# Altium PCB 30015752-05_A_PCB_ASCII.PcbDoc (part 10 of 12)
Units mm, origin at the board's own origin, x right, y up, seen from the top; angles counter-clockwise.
Board outline 100.05 x 72 mm, 10 copper layers (Top, GND_2, Signal_3, Signal_4, PWR_5, GND_6, Signal_7, Signal_8, GND_9, Bottom), stack 1.493 mm thick; 577 components, 546 nets, 2389 pads, 1412 vias.
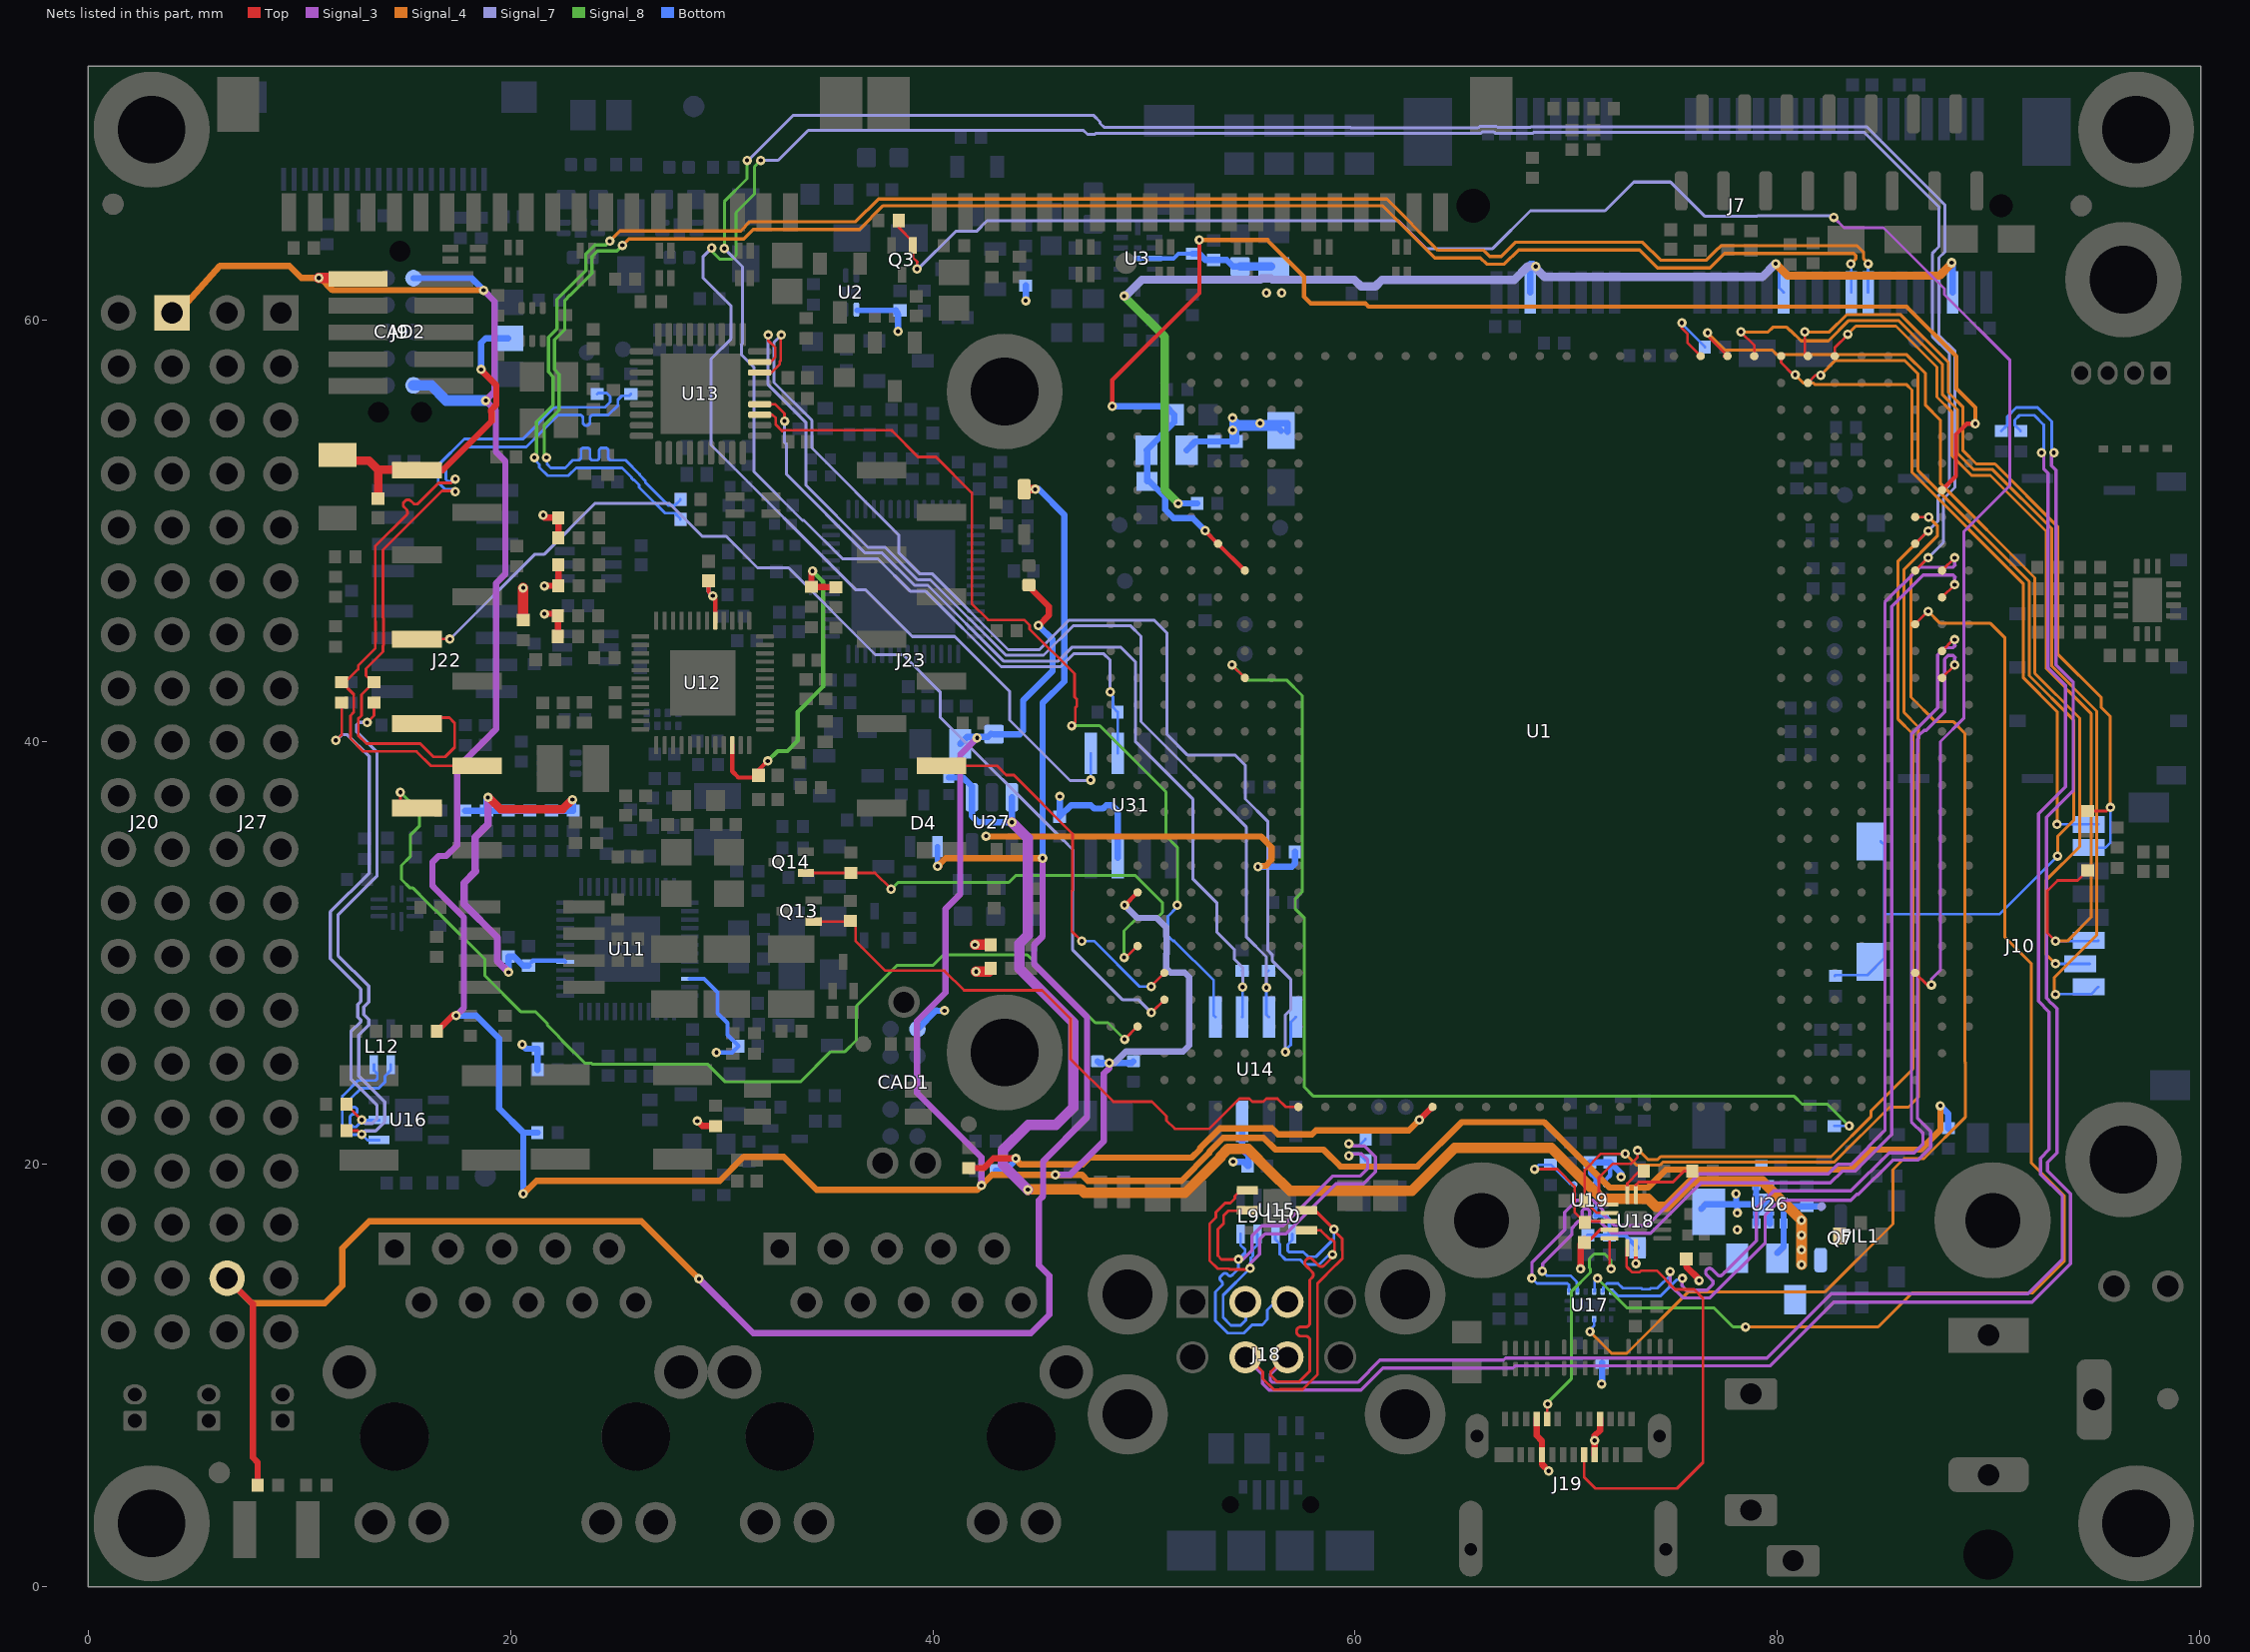
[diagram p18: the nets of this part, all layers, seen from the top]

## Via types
v1: diameter 0.45, hole 0.2, Top to Bottom, tented both sides, 1412 vias

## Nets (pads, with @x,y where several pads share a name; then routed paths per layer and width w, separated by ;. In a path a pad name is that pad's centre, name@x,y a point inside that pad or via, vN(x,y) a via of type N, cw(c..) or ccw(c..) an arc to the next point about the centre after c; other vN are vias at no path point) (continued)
USB_PCIe_D_N: J7.36 R229.2 | length 85.4
  Signal_8 w0.157: v1(21.7,53.475) 21.7,53.554 21.596,53.659 21.596,55.012 22.297,55.713 22.297,57.423 22.075,57.645 22.075,59.045 22.569,59.539 22.569,60.928 22.822,61.181 22.831,61.181 23.85,62.2 23.85,63 24.106,63.256 25.031,63.256 v1(25.3,63.525)
  Signal_4 w0.157: v1(25.3,63.525) 25.608,63.833 31.05,63.833 31.492,64.275 36.525,64.275 37.653,65.403 61.297,65.403 63.777,62.923 65.94,62.923 66.229,62.634 67.071,62.634 67.74,63.303 73.476,63.303 74.322,62.457 76.807,62.457 77.351,63.001 77.356,63.001 77.491,63.136 83.624,63.136 83.716,63.043 83.716,62.889 83.48,62.653 v1(83.48,62.64)
  Bottom w0.132: v1(21.7,53.475) 21.727,53.448 21.727,53.167 21.912,52.982 22.586,52.982 22.951,53.347 23.125,53.347 23.201,53.347 ccw(c23.201,53.476) 23.331,53.476 23.331,53.798 cw(c23.46,53.798) 23.46,53.928 23.633,53.928 cw(c23.633,53.798) 23.763,53.798 23.763,53.476 ccw(c23.892,53.476) 23.892,53.347 24.065,53.347 ccw(c24.065,53.476) 24.195,53.476 24.195,53.798 cw(c24.324,53.798) 24.324,53.928 24.497,53.928 cw(c24.497,53.798) 24.627,53.798 24.627,53.476 ccw(c24.757,53.476) 24.757,53.347 25.059,53.347 25.275,53.347 25.442,53.347 26.107,52.682 26.107,52.652 26.386,52.372 26.386,52.291 26.983,51.694 26.986,51.694 27.471,51.209 27.779,51.209 28.045,51.475 R229.2@28.045,51.5 ; v1(83.48,62.64) 83.49,62.64 83.5,62.65 83.5,62.64 J7.36@83.5,61.3
USB_PCIe_D_P: J7.38 R228.2 | length 85.2
  Signal_8 w0.157: v1(21.123,53.475) 21.123,53.554 21.227,53.659 21.227,55.164 22.013,55.949 22.013,57.306 21.791,57.528 21.791,59.163 22.201,59.573 22.201,60.976 23.566,62.341 23.566,63.118 23.988,63.54 24.515,63.54 v1(24.7,63.725)
  Signal_4 w0.157: v1(24.7,63.725) 25.176,64.201 30.897,64.201 31.34,64.643 36.347,64.643 37.423,65.719 61.502,65.719 63.93,63.291 66.092,63.291 66.382,63.002 66.918,63.002 67.588,63.671 73.629,63.671 74.475,62.825 76.654,62.825 77.198,63.369 77.203,63.369 77.338,63.504 83.776,63.504 84.084,63.196 84.084,62.889 84.3,62.673 v1(84.3,62.65)
  Bottom w0.132: v1(21.123,53.475) 21.123,53.389 21.358,53.154 21.358,53.015 21.76,52.614 22.739,52.614 23.103,52.978 25.29,52.978 25.739,52.529 25.739,52.499 25.817,52.421 25.849,52.421 26.094,52.176 26.094,52.062 26.83,51.326 26.834,51.326 27.319,50.841 27.779,50.841 28.045,50.575 R228.2@28.045,50.55 ; J7.38@84.3,61.3 v1(84.3,62.65)
USB_PWR: Q3.G R144.2 U1.C24 | length 93
  Top w0.127: R144.2@38.38,64.7 38.38,64.37 39.05,63.7 Q3.G@39.05,63.515 39.05,62.95 39.26,62.74 39.252,62.732 v1(39.252,62.403) ; U1.C24@86.53,29.07 87.1,28.5 v1(87.3,28.5)
  Signal_3 w0.142: v1(82.675,64.85) 83.165,64.36 85.029,64.36 87.912,61.476 87.912,61.188 91.019,58.081 91.019,52.156 88.843,49.98 88.843,41.143 87.725,40.025 87.725,29.2 87.3,28.775 v1(87.3,28.5)
  Signal_7 w0.142: v1(39.252,62.403) 39.257,62.403 39.28,62.38 41.088,64.188 42.067,64.188 42.566,64.687 62.056,64.687 63.369,63.374 66.518,63.374 68.31,65.165 71.842,65.165 73.2,66.523 74.937,66.523 76.551,64.909 79.056,64.909 79.067,64.92 82.605,64.92 v1(82.675,64.85)
USB_SS3_ALERT_N: R147.2 U1.C7 U18.10 | length 49.8
  Top w0.127: U18.10@72.05,17.7 71.455,17.7 R147.2@70.88,18.275 70.88,19.73 71.65,20.5 v1(72.8,20.5) ; U1.C7@86.53,50.66 87.165,50.66 v1(87.175,50.65)
  Signal_4 w0.142: v1(72.8,20.5) 73.342,19.958 74.439,19.958 74.584,20.102 82.702,20.102 85.313,22.713 86.213,22.713 86.69,23.19 86.69,40.71 85.994,41.406 85.994,48.173 87.573,49.752 87.573,50.252 v1(87.175,50.65)
USB_SS3_BUS_SEL: U1.C11 U17.12 | length 60.8
  Top w0.127: U1.C11@86.53,45.58 87.14,46.19 v1(87.15,46.19)
  Signal_8 w0.142: v1(71.48,14.6) 72.88,13.2 77,13.2 77.9,12.3 v1(78.5,12.3)
  Signal_4 w0.142: v1(78.5,12.3) 84.775,12.3 86.375,13.9 92.075,13.9 93.6,15.425 93.6,18.5 92.04,20.06 92.04,29.492 90.787,30.746 90.787,44.933 90.1,45.62 87.72,45.62 v1(87.15,46.19)
  Bottom w0.127: U17.12@71.325,13.975 71.353,14.003 71.353,14.473 v1(71.48,14.6)
USB_SS3_CC1: J19.A5 U18.13 | length 11.6
  Top w0.127: J19.A5@69.1,7.94 69.1,8.625 v1(69.125,8.65) ; U18.13@72.05,16.5 72.05,15.125 v1(72.125,15.05)
  Signal_8 w0.142: v1(69.125,8.65) 69.125,8.723 70.237,9.836 70.237,13.964 71.148,14.875 71.148,15.054 71.102,15.1 71.102,15.527 71.325,15.75 71.825,15.75 72.125,15.45 v1(72.125,15.05)
USB_SS3_CC2: J19.B5 U18.14 | length 20.4
  Top w0.127: J19.B5@70.85,6.24 70.85,5.175 71.375,4.65 75.25,4.65 76.479,5.879 76.479,13.655 76.055,14.079 75.175,14.079 74.289,14.965 73.553,14.965 73.472,14.884 73.128,14.884 72.884,15.128 72.884,15.15 72.859,15.175 72.859,16.009 U18.14@72.9,16.05
USB_SS3_INT_B: U1.C8 U18.9 U31.1 | length 164.5
  Top w0.127: U18.9@72.05,18.1 71.7,18.1 71.55,18.25 71.55,19.375 72.2,20.025 73.075,20.025 73.379,20.329 v1(73.379,20.651) ; U1.C8@86.53,49.39 87.14,50 v1(87.15,50)
  Signal_8 w0.142: v1(29.525,63.4) 29.525,63.25 29.9,62.875 30.5,62.875 30.675,63.05 30.675,65.075 31.55,65.95 31.55,67.25 v1(31.85,67.55)
  Signal_4 w0.142: v1(73.379,20.651) 73.449,20.651 73.873,20.227 74.328,20.227 74.472,20.371 82.545,20.371 84.447,22.274 84.447,22.547 86.421,24.521 86.421,40.379 85.725,41.075 85.725,48.575 v1(87.15,50)
  Signal_7 w0.142: v1(29.525,63.4) 29.127,63.002 29.127,61.973 30.45,60.65 30.45,59.1 29.5,58.15 29.5,54.065 36.364,47.202 36.823,47.202 39.025,45 41.04,45 43.641,42.399 43.641,41.039 46.503,38.177 47.452,38.177 v1(47.475,38.2) ; v1(31.85,67.55) 32.675,67.55 34.098,68.973 47.128,68.973 47.325,68.777 47.675,68.777 47.739,68.84 59.675,68.84 59.693,68.823 65.943,68.823 66.013,68.892 66.587,68.892 66.639,68.84 68.418,68.84 68.447,68.869 84.131,68.869 87.66,65.34 87.66,63.46 87.34,63.14 87.34,59.215 88.15,58.405 88.15,53.885 88.142,53.877 88.142,52.167 87.598,51.623 87.598,50.448 v1(87.15,50)
  Bottom w0.127: v1(47.475,38.2) 47.475,39.46 U31.1@47.485,39.47
USB_SS3_RX_N: U1.B12 U17.14 | length 46.7
  Top w0.132: U1.B12@87.8,44.31 88.373,44.883 v1@88.404,44.914 ; v1(88.404,44.852) v1@88.404,44.914 ; v1@88.41,44.92 v1@88.404,44.914
  Signal_3 w0.157: v1(75.5,14.6) 75.481,14.581 75.481,14.244 75.682,14.043 76.668,14.043 76.9,14.275 76.913,14.288 ccw(c76.799,14.401) 76.913,14.515 76.653,14.775 cw(c76.766,14.889) 76.653,15.003 76.678,15.028 cw(c76.792,14.914) 76.905,15.028 77.165,14.768 ccw(c77.279,14.882) 77.393,14.768 77.532,14.907 77.538,14.913 79.012,16.388 79.012,17.912 79.841,18.741 81.15,18.741 ; 81.151,18.74 83.484,18.74 85.294,20.55 86.482,20.55 86.9,20.968 86.9,21.475 86.354,22.021 86.354,39.642 86.36,39.649 86.36,40.005 86.354,40.012 86.354,40.375 87.6,41.621 87.6,44.122 87.947,44.469 88.328,44.469 88.42,44.561 88.404,44.577 v1(88.404,44.852)
  Bottom w0.132: U17.14@72.125,13.975 72.245,13.975 72.456,13.764 74.471,13.764 75.246,14.539 75.439,14.539 v1(75.5,14.6)
USB_SS3_RX_P: U1.B13 U17.13 | length 46.8
  Top w0.132: U1.B13@87.8,43.04 88.408,43.648 88.41,43.65 88.408,43.652 v1(88.404,43.652)
  Signal_3 w0.157: v1(74.925,14.925) 74.925,14.279 75.529,13.675 76.821,13.675 79.425,16.279 79.425,17.6 80.125,18.3 83.491,18.3 83.772,18.581 83.845,18.581 85.464,20.2 86.653,20.2 87.268,20.816 87.268,21.553 86.638,22.183 86.638,39.524 86.644,39.531 86.644,40.123 86.638,40.129 86.638,40.138 86.699,40.199 86.699,40.305 86.951,40.558 87.058,40.558 87.925,41.425 87.925,43.926 88.1,44.101 88.328,44.101 88.42,44.009 88.404,43.993 v1(88.404,43.652)
  Bottom w0.132: U17.13@71.725,13.975 71.757,14.007 71.757,14.178 71.934,14.354 72.454,14.354 72.677,14.132 73.556,14.132 73.605,14.083 73.952,14.083 74.001,14.132 74.318,14.132 74.925,14.739 v1(74.925,14.925)
USB_SS3_SCL: R173.2 U18.8 | length 1.3
  Top w0.127: U18.8@72.9,18.55 72.9,19.1 R173.2@73.45,19.65
USB_SS3_SDA: R174.2 U18.7 | length 3.4
  Top w0.127: U18.7@73.3,18.55 73.3,19.025 73.436,19.161 75.061,19.161 75.58,19.68 R174.2@75.98,19.68
USB_SS3_SW_PWR: R235.1 U1.C9 U17.3 U31.2 | length 172.9
  Top w0.127: U1.C9@86.53,48.12 87.14,48.73 v1(87.15,48.73)
  Signal_8 w0.142: v1(30.125,63.375) 30.125,65.597 31.2,66.672 v1(31.2,67.55)
  Signal_4 w0.142: v1(71.125,12.075) 72.15,11.05 72.875,11.05 75.775,13.95 82.25,13.95 85.475,17.175 85.475,19.75 86,20.275 86.95,20.275 88.902,22.227 88.902,24.826 88.875,24.854 88.875,40.425 88.325,40.975 87.475,40.975 86.325,42.125 86.325,47.905 v1(87.15,48.73)
  Signal_7 w0.142: v1(30.125,63.375) 30.988,62.512 30.988,58.877 30.948,58.837 30.948,58.327 31.525,57.75 31.525,52.802 33.825,50.502 33.898,50.502 35.725,48.675 37.4,48.675 38.925,47.15 39.652,47.15 43.232,43.569 46.056,43.569 46.662,44.175 48.1,44.175 48.4,43.875 v1(48.4,42.375) ; v1(31.2,67.55) 31.252,67.55 33.004,69.302 33.004,69.304 33.371,69.671 47.627,69.671 47.923,69.375 47.923,69.302 48.115,69.11 59.787,69.11 59.805,69.092 65.832,69.092 65.902,69.162 66.698,69.162 66.75,69.11 68.307,69.11 68.336,69.139 84.242,69.139 87.929,65.452 87.929,63.204 87.66,62.935 87.66,59.276 88.419,58.517 88.419,53.773 88.412,53.765 88.412,52.056 87.867,51.512 87.867,49.447 v1(87.15,48.73)
  Bottom w0.127: v1(48.4,42.375) 48.4,42.288 48.534,42.154 48.534,41.646 R235.1@48.755,41.425 U31.2@48.755,39.47 ; v1(71.125,12.075) 71.125,12.162 71.325,12.362 U17.3@71.325,12.675
USB_SS3_TX_N: U1.B9 U17.9 | length 54.1
  Top w0.132: U1.B9@87.8,48.12 88.406,48.726 v1@88.407,48.727 ; v1(88.404,48.727) v1@88.407,48.727 ; v1@88.41,48.73 v1@88.407,48.727
  Signal_3 w0.157: v1(68.375,14.6) 68.375,15.35 69.925,16.9 69.925,17.725 70.5,18.3 71.275,18.3 71.734,17.841 71.734,17.668 72.303,17.1 73.84,17.1 76.29,19.55 82.425,19.55 82.875,20 83.5,20 85.1,21.6 85.1,46.621 86.758,48.279 88.328,48.279 88.42,48.371 88.404,48.387 v1(88.404,48.727)
  Bottom w0.132: v1(68.375,14.6) 68.613,14.362 70.054,14.362 70.141,14.275 70.141,14.207 70.125,14.191 U17.9@70.125,13.975
USB_SS3_TX_P: U1.B10 U17.10 | length 53.2
  Top w0.132: U1.B10@87.8,46.85 88.403,47.453 v1@88.404,47.454 ; v1(88.404,47.452) v1@88.404,47.454 ; v1@88.41,47.46 v1@88.404,47.454
  Signal_3 w0.132: v1(68.875,14.95) v1@68.888,14.963
  Signal_3 w0.157: v1@68.888,14.963 68.888,15.3 70.272,16.684 70.272,16.979 70.575,17.3 70.593,17.3 ccw(c70.593,17.461) 70.754,17.461 70.754,17.735 cw(c70.915,17.735) 70.915,17.896 70.95,17.896 cw(c70.95,17.735) 71.111,17.735 71.111,17.461 ccw(c71.272,17.461) 71.272,17.3 71.469,17.3 71.475,17.3 71.582,17.3 72.15,16.732 73.993,16.732 76.386,19.125 82.521,19.125 83.077,19.681 83.681,19.681 85.425,21.425 85.425,46.425 86.911,47.911 88.328,47.911 88.42,47.819 88.404,47.803 v1(88.404,47.452)
  Bottom w0.132: v1(68.875,14.95) 69.095,14.73 70.206,14.73 70.509,14.428 70.509,14.207 70.525,14.191 U17.10@70.525,13.975
USBC_FAULT_N: R148.2 R149.2 U18.11 U19.A4 | length 7.7
  Top w0.127: v1(68.5,19.775) 69.575,19.775 70.396,18.954 70.396,17.734 R148.2@70.88,17.25 70.93,17.3 U18.11@72.05,17.3
  Bottom w0.127: v1(68.5,19.775) 68.705,19.98 R149.2@69.25,19.98 69.275,19.98 70.172,19.083 70.347,19.083 U19.A4@70.38,19.05
USBC_VBUS: C100.2 C103.2 C106.2 C107.2 D8.K J19.A4 J19.A9 J19.B4 J19.B9 U18.15 U19.C2 U19.D1 U19.D2 | length 12.9
  Top w0.2: v1(73.3,15.3) U18.15@73.3,16.05
  Top w0.3: J19.A4@68.6,7.94 68.6,7.15 68.85,6.9 J19.B9@68.85,6.24 68.85,5.8 v1(69.175,5.475) ; J19.B4@71.35,6.24 v1(71.35,6.925) 71.35,7.15 71.6,7.4 J19.A9@71.6,7.94 ; C100.2@75.69,15.525 75.69,15.16 76.3,14.55 v1@76.3,14.525
  Bottom w0.2: C107.2@71.025,16.635 C106.2@72.05,16.635 ; U19.C2@71.38,18.05 U19.D2@71.38,17.55 U19.D1@71.88,17.55 72.05,17.38 C106.2@72.05,16.635 ; v1(73.3,15.3) 73.3,15.92 73.275,15.945 D8.K@73.38,16.05 72.795,16.635 C106.2@72.05,16.635
  Bottom w0.3: v1(71.675,9.6) 71.7,9.625 C103.2@71.7,10.615
  other v1: 76.3,14.5
USBH1_D_N: J18.A2 L9.2 R242.1 U15.1 | length 24.9
  Top w0.132: U15.1@54.9,18.775 54.581,18.775 54.306,18.5 54.306,18.377 54.098,18.169 53.844,18.169 53.407,17.732 53.407,17.478 53.107,17.178 53.107,15.447 53.497,15.057 54.018,15.057 54.05,15.025 54.975,15.025 v1(55.025,15.075)
  Signal_3 w0.157: v1(55.025,15.075) 55.025,15.302 55.469,15.746 55.469,15.753 55.475,15.759 55.475,16.443 55.747,16.715 56.736,16.715 59.098,19.077 60.398,19.077 60.968,19.647 60.968,20.356 60.453,20.872 59.804,20.872 v1(59.7,20.976)
  Bottom w0.132: J18.A2@54.801,13.485 54.825,13.461 54.825,12.621 54.579,12.375 54.125,12.375 53.75,12.75 53.75,13.804 v1@55.023,15.077 ; v1@55.068,15.122 55.068,15.572 55.159,15.663 55.159,15.968 55.375,16.184 L9.2@55.375,16.7 ; v1(59.7,20.976) 59.804,20.872 60.167,20.872 R242.1@60.495,21.2
USBH1_D_P: J18.A3 L9.3 R243.1 U15.2 | length 24.8
  Top w0.132: v1(54.475,15.5) 53.675,15.5 53.5,15.675 53.5,16.925 53.775,17.2 53.775,17.579 53.997,17.801 54.876,17.801 U15.2@54.9,17.825
  Signal_3 w0.157: v1(54.475,15.5) 54.702,15.5 55.125,15.923 55.125,16.614 55.594,17.083 56.583,17.083 58.945,19.445 60.245,19.445 60.6,19.8 60.6,20.203 60.3,20.503 59.804,20.503 v1(59.7,20.399)
  Bottom w0.132: L9.3@54.575,16.7 54.575,16.184 54.791,15.968 54.791,15.816 v1(54.475,15.5) 54.475,15.05 54.262,14.837 54.175,14.75 cw(c54.083,14.842) 53.992,14.75 53.935,14.807 ccw(c53.843,14.715) 53.752,14.807 53.629,14.684 ccw(c53.721,14.593) 53.629,14.501 53.686,14.444 cw(c53.594,14.353) 53.686,14.261 53.625,14.2 53.382,13.957 53.382,12.597 53.972,12.007 54.732,12.007 55.124,12.399 55.599,12.399 55.85,12.65 55.85,13.1 56.235,13.485 J18.A3@56.801,13.485 ; v1(59.7,20.399) 59.804,20.503 60.167,20.503 R243.1@60.495,20.175
USBH1_OC_N: R142.1 U13.13 U14.2 | length 44.8
  Top w0.127: U13.13@31.8,56 32.525,56 32.975,55.55 v1(32.975,55.2)
  Signal_7 w0.142: v1(32.975,55.2) 32.975,54.198 33.073,54.1 33.073,52.677 36.794,48.956 37.601,48.956 39.137,47.419 39.763,47.419 43.344,43.838 45.944,43.838 46.606,44.5 48.894,44.5 49.591,43.803 49.591,40.031 52.311,37.311 52.311,33.524 53.46,32.375 53.46,30.99 54.271,30.179 54.271,29.729 54.675,29.325 v1(54.675,28.4)
  Bottom w0.127: R142.1@54.65,29.17 54.675,29.145 v1@54.675,28.405 ; U14.2@54.655,26.97 54.675,26.99 v1(54.675,28.4) v1@54.675,28.405 ; v1@54.655,28.425 v1@54.675,28.405
USBH1_PWR_EN: U13.12 U14.1 | length 43.7
  Top w0.127: U13.12@31.8,55.5 32.4,55.5 32.559,55.341 32.559,55.028 32.862,54.725 ; 32.85,54.775 38.063,54.775 ; 38.075,54.725 39.3,53.5 40.15,53.5 41.85,51.8 41.85,46.55 42.616,45.784 44.335,45.784 44.584,45.535 44.584,45.353 46.71,43.228 46.71,42.138 46.816,42.032 46.816,41.688 46.75,41.622 46.75,40.95 v1(46.575,40.775)
  Signal_8 w0.142: v1(46.575,40.775) 47.906,40.775 51.042,37.638 51.042,35.55 51.575,35.017 v1(51.575,32.275)
  Bottom w0.127: v1(51.575,32.275) 51.575,32.189 51.137,31.751 51.137,30.829 51.38,30.586 51.426,30.586 53.306,28.707 53.306,27.05 U14.1@53.385,26.97
USBH2_D_N: J18.B2 L10.2 R238.1 U15.5 | length 105.3
  Top w0.132: J18.B2@54.801,10.865 54.942,10.865 55.632,10.175 55.632,9.847 56.147,9.332 56.419,9.332 56.436,9.348 57.519,9.348 58.225,10.054 58.225,14.372 59.105,15.252 59.121,15.252 59.398,15.529 59.398,15.921 59.393,15.926 59.393,16.478 v1@58.973,16.898 ; U15.5@57.7,17.825 58.1,17.825 v1(59,16.925)
  Signal_3 w0.157: J18.B2@54.801,10.865 55.617,10.049 55.617,9.622 55.932,9.307 60.278,9.307 61.321,10.35 67.471,10.35 67.575,10.454 72.45,10.454 79.655,10.454 82.676,13.475 92.077,13.475 93.884,15.282 93.884,18.616 92.8,19.7 92.8,20.104 93.243,20.547 93.243,27.377 93.001,27.619 92.997,27.619 92.744,27.872 92.744,36.447 94.021,37.724 94.021,42.835 93.2,43.656 93.2,52.875 92.993,53.082 92.993,53.596 v1(93.098,53.7)
  Bottom w0.132: L10.2@57.025,16.7 57.025,16.425 56.809,16.209 56.809,15.9 56.859,15.85 57.553,15.85 57.778,15.625 58.15,15.625 59,16.475 v1(59,16.925) ; R238.1@90.605,54.73 90.881,55.006 90.881,55.403 91.322,55.843 92.328,55.843 92.993,55.178 92.993,53.804 v1(93.098,53.7)
USBH2_D_P: J18.B3 L10.3 R239.1 U15.4 | length 102.8
  Top w0.132: J18.B3@56.801,10.865 56.69,10.865 56,10.175 56,10 56.284,9.716 57.366,9.716 57.857,10.207 57.857,11.65 57.857,11.672 ccw(c57.662,11.672) 57.662,11.866 57.426,11.866 cw(c57.426,12.06) 57.232,12.06 57.232,12.104 cw(c57.426,12.104) 57.426,12.298 57.662,12.298 ccw(c57.662,12.493) 57.857,12.493 57.857,12.575 57.857,14.525 57.95,14.618 57.965,14.634 ccw(c57.828,14.771) 57.965,14.909 57.676,15.197 cw(c57.814,15.335) 57.676,15.472 57.707,15.503 cw(c57.844,15.365) 57.982,15.503 58.271,15.214 ccw(c58.408,15.352) 58.546,15.214 58.682,15.35 v1@58.991,15.659 ; U15.4@57.7,16.875 58.381,16.875 58.804,16.452 58.898,16.452 59.025,16.325 v1@59.025,15.725
  Signal_3 w0.157: J18.B3@56.801,10.865 55.985,10.049 55.985,9.775 56.085,9.675 60.125,9.675 61.175,10.725 67.029,10.725 67.126,10.822 79.502,10.822 82.555,13.875 91.875,13.875 93.5,15.5 93.5,18.5 92.468,19.532 92.468,20.293 92.875,20.7 92.875,27.224 92.376,27.723 92.376,36.6 93.653,37.877 93.653,42.683 92.825,43.51 92.825,52.729 92.625,52.929 92.625,53.596 v1(92.521,53.7)
  Bottom w0.132: L10.3@56.225,16.7 56.225,16.45 56.441,16.234 56.441,15.747 56.707,15.482 57.4,15.482 57.625,15.257 58.303,15.257 v1@58.848,15.802 ; v1@58.91,15.865 58.91,15.74 v1(58.925,15.725) ; R239.1@91.525,54.73 91.249,55.006 91.249,55.25 91.474,55.475 92.175,55.475 92.625,55.025 92.625,53.804 v1(92.521,53.7)
USBH2_OC_N: R143.1 U13.17 U14.3 | length 51.2
  Top w0.127: U13.17@31.8,58 32.3,58 32.541,58.241 32.541,58.685 32.2,59.025 v1(32.2,59.275)
  Signal_7 w0.142: v1(32.2,59.275) 32.2,56.923 34,55.123 34,52.15 36.925,49.225 37.739,49.225 39.276,47.688 39.875,47.688 43.455,44.108 45.25,44.108 46.642,45.5 49.375,45.5 49.86,45.015 49.86,40.965 54.84,35.985 54.84,30.785 55.8,29.825 v1(55.8,28.375)
  Bottom w0.127: R143.1@55.9,29.17 55.8,29.07 v1(55.8,28.375) 55.8,27.095 U14.3@55.925,26.97
USBH2_PWR_EN: U13.16 U14.4 | length 56.4
  Top w0.127: U13.16@31.8,57.5 32.35,57.5 32.75,57.9 32.75,58.027 32.795,58.072 32.795,59.245 v1(32.825,59.275)
  Signal_7 w0.142: v1(32.825,59.275) 32.475,58.925 32.475,57.029 34.269,55.235 34.269,53.925 38.4,49.794 38.4,48.945 39.387,47.958 39.986,47.958 43.567,44.377 45.052,44.377 46.45,45.775 50.475,45.775 51.1,45.15 51.1,40.35 52.075,39.375 54.325,39.375 54.8,38.9 54.8,37.3 55.875,36.225 55.875,30.131 56.069,29.937 56.069,29.651 56.948,28.772 56.948,27.321 56.7,27.073 v1(56.7,25.325)
  Bottom w0.127: v1(56.7,25.325) 56.7,25.396 56.959,25.654 56.959,26.733 U14.4@57.195,26.97
USDHC1_CD_B: J10.9 J10.10 R54.2 U1.G2 | length 49.8
  Top w0.127: U1.G2@81.45,57.01 81.815,57.375 v1(82.05,57.375)
  Signal_4 w0.142: v1(82.05,57.375) 82.751,58.076 86.022,58.076 86.65,57.448 86.65,52.881 91.931,47.6 91.931,43.142 94.006,41.067 ; v1(93.275,34.6) 93.275,35.527 94.051,36.303 94.051,41.022 94.006,41.067
  Bottom w0.127: R54.2@82.725,28.93 82.759,28.964 84.264,28.964 85.071,29.77 85.071,31.85 ; J10.10@84.9,35.3 85.071,35.129 85.071,31.85 ; v1(93.275,34.6) 90.52,31.845 85.698,31.845 85.692,31.85 85.071,31.85
USDHC1_CLK: R58.1 U1.L1 | length 3.5
  Top w0.127: v1(75.475,59.85) 75.475,59.603 75.747,59.33 75.747,58.903 U1.L1@76.37,58.28
  Bottom w0.127: v1(75.475,59.85) 75.475,59.82 76.57,58.725 R58.1@76.57,58.7
USDHC1_CMD: J10.3 R53.1 U1.F1 | length 45.1
  Top w0.127: U1.F1@82.72,58.28 82.72,58.67 83.34,59.29 v1(83.34,59.32) ; v1(93.175,30.575) 92.784,30.966 92.784,32.959 93.275,33.45 94.23,33.45 R53.1@94.7,33.92
  Signal_4 w0.142: v1(83.34,59.32) 83.718,59.698 85.625,59.698 87.562,57.762 87.562,56.336 88.258,55.639 88.258,53.574 89.202,52.631 90.088,52.631 92.738,49.981 92.738,43.477 94.813,41.402 94.859,41.356 94.859,31.694 93.74,30.575 v1(93.175,30.575)
  Bottom w0.127: v1(93.175,30.575) 95.175,30.575 J10.3@95.2,30.6
USDHC1_DATA0: J10.7 R55.1 U1.G1 | length 37.5
  Top w0.127: v1(81.3,59.425) 81.3,58.43 U1.G1@81.45,58.28 ; R55.1@94.7,36.73 95.605,36.73 v1(95.775,36.9)
  Signal_4 w0.142: v1(81.3,59.425) 82.466,59.425 83.277,60.237 85.848,60.237 88.1,57.985 88.1,56.559 88.797,55.862 88.797,53.798 89.425,53.17 90.311,53.17 93.277,50.204 93.277,44.178 95.352,42.103 95.352,41.625 95.775,41.202 v1(95.775,36.9)
  Bottom w0.127: J10.7@95.2,35 95.55,35 95.775,35.225 v1(95.775,36.9)
USDHC1_DATA1: J10.8 U1.H1 | length 32.4
  Top w0.127: U1.H1@80.18,58.28 80.18,57.97 80.756,57.394 v1(80.844,57.394)
  Signal_4 w0.142: v1(80.844,57.394) 81.242,56.995 81.716,56.995 81.771,56.94 86.11,56.94 86.375,56.675 86.375,52.775 91.661,47.489 91.661,43.031 93.25,41.442 v1(93.25,36.1)
  Bottom w0.127: v1(93.25,36.1) J10.8@94.75,36.1 J10.8@95.2,36.1
USDHC1_DATA2: J10.1 U1.J1 | length 49
  Top w0.127: v1(78.275,59.425) 78.91,58.79 U1.J1@78.91,58.28
  Signal_4 w0.142: v1(78.275,59.425) 79.57,59.425 79.788,59.643 80.452,59.643 80.615,59.48 80.647,59.48 81.125,59.002 82.423,59.002 83.389,59.967 85.737,59.967 87.831,57.873 87.831,56.447 88.528,55.75 88.528,53.686 89.313,52.9 90.199,52.9 93.008,50.092 93.008,43.588 95.083,41.513 95.128,41.468 95.128,30.855 93.129,28.855 93.129,28.096 v1(93.175,28.05)
  Bottom w0.127: v1(93.175,28.05) 93.189,28.063 94.864,28.063 J10.1@95.2,28.4
USDHC1_DATA3: J10.2 U1.K1 | length 46.2
  Top w0.127: v1(76.7,59.375) 76.7,59.22 U1.K1@77.64,58.28 U1.K1@77.48,58.28
  Signal_4 w0.142: v1(76.7,59.375) 77.516,58.559 79.766,58.559 79.98,58.345 86.134,58.345 87.023,57.456 87.023,55.949 87.72,55.252 87.72,52.259 92.2,47.779 92.2,43.254 94.275,41.179 94.32,41.133 94.32,35.047 92.752,33.478 92.752,29.923 v1(93.175,29.5)
  Bottom w0.127: v1(93.175,29.5) J10.2@94.35,29.5 J10.2@94.8,29.5
USER_LED0: Q14.G R108.1 U1.AM23 | length 22.8
  Top w0.127: Q14.G@33.99,33.8 R108.1@36.12,33.8 37.26,33.8 v1(38.025,33.035) ; v1(49.06,29.8) 49.16,29.8 U1.AM23@49.7,30.34
  Signal_8 w0.142: v1(38.025,33.035) 38.035,33.035 38.35,33.35 43.6,33.35 43.925,33.675 49.6,33.675 50.875,32.4 50.875,31.925 50.65,31.7 49.7,31.7 49.06,31.06 v1(49.06,29.8)
USER_LED1: Q13.G R109.1 U1.AF29 | length 29.6
  Top w0.127: Q13.G@34.35,31.5 36.08,31.5 R109.1@36.1,31.52 36.125,31.52 36.346,31.299 36.346,30.569 37.741,29.175 40.55,29.175 41.48,28.245 45.18,28.245 46.525,26.9 46.525,24.987 48.548,22.964 50.373,22.964 51.066,22.272 51.066,22.077 51.458,21.684 53.092,21.684 54.518,23.11 54.987,23.11 55.133,22.964 55.651,22.964 55.797,23.11 56.326,23.11 56.717,22.72 U1.AF29@57.32,22.72
VCC_LICELL: D4.1 D13.K J27.38 R18.1 | length 104.5
  Top w0.3: J27.38@6.56,14.6 7.787,13.373 7.787,6.121 8.02,5.888 R18.1@8.02,4.8
  Top w0.4: D13.K@44.325,51.97 v1(44.85,51.97)
  Signal_3 w0.3: v1(28.925,14.575) 31.5,12 44.65,12 45.525,12.875 45.525,14.725 45.025,15.225 45.025,18.3 45.223,18.498 45.223,20.148 47.308,22.233 47.308,26.982 44.798,29.492 44.798,30.398 45.2,30.8 v1(45.2,34.5)
  Signal_4 w0.3: J27.38@6.56,14.6 7.737,13.423 11.198,13.423 12.033,14.258 12.033,16.033 13.3,17.3 26.2,17.3 28.962,14.537 28.925,14.5 v1(28.925,14.575) ; v1@40.319,34.119 v1(40.219,34.119) 40.6,34.5 v1(45.2,34.5)
  Bottom w0.25: v1(40.219,34.119) D4.1@40.219,35.059
  Bottom w0.3: v1(44.85,51.97) 45.015,51.97 46.225,50.76 46.225,42.875 45.2,41.85 v1(45.2,34.5)
VCC_MCA: C143.2 C162.2 CAD2.1 CAD2.5 J9.1 J20.1 R15.2 R17.2 R31.2 R162.2 R259.2 R260.2 U1.AM21 | length 208.2
  Top w0.2: v1(49.08,32.27) 49.09,32.27 U1.AM21@49.7,32.88
  Top w0.3: R15.2@16.5,26.3 17.25,27.05 v1(17.425,27.05) ; C162.2@44.55,47.44 44.55,47.373 45.502,46.421 45.502,46.005 45.022,45.525 v1(45,45.525)
  Top w0.5: v1(10.92,61.98) 12.728,61.98 J9.1@12.768,61.94
  Signal_3 w0.3: v1(17.425,27.05) 17.791,27.416 17.791,31.692 16.475,33.009 16.475,33.015 16.299,33.191 16.299,34.31 16.593,34.604 16.954,34.604 17.468,35.118 17.468,38.768 19.313,40.613 19.313,47.516 19.75,47.953 19.75,53.3 19.3,53.75 19.3,55.7 v1(18.825,56.175) 19.25,56.6 19.25,60.875 v1(18.725,61.4) ; v1(42.1,40.2) 41.3,39.4 41.3,32.8 40.6,32.1 40.6,28.143 39.25,26.793 39.25,23.375 42.3,20.325 v1(42.3,19) ; v1(45.8,19.5) 46.5,19.5 48.1,21.1 48.1,24.3 48.352,24.552 v1(48.352,24.801)
  Signal_4 w0.3: J20.1@4.325,60.425 6.226,62.546 9.519,62.546 10.086,61.98 v1(10.92,61.98) 10.985,61.98 11.565,61.4 v1(18.725,61.4) ; v1(20.6,18.6) 21.227,19.227 29.91,19.227 31.031,20.348 32.943,20.348 34.491,18.8 42.1,18.8 v1(42.3,19) 42.8,19.5 v1(45.8,19.5) 47.07,19.5 47.345,19.225 51.78,19.225 53.096,20.541 53.096,20.593 53.757,21.254 55.671,21.254 56.225,20.7 58.5,20.7 59.303,19.897 62.947,19.897 65.05,22 68.95,22 72.052,18.898 73.872,18.898 74.728,19.754 83.454,19.754 84.4,20.7 86.8,20.7 87.725,21.625 v1(87.725,22.775)
  Signal_7 w0.3: v1(48.352,24.801) 48.601,24.801 49.15,25.35 51.85,25.35 52.136,25.636 52.136,28.864 51.925,29.075 51.271,29.075 51.051,29.296 51.051,29.959 51.071,29.98 51.071,30.773 51.051,30.794 51.051,31.224 50.6,31.675 49.675,31.675 v1(49.08,32.27)
  Bottom w0.3: CAD2.1@15.4,61.97 18.155,61.97 v1(18.725,61.4) ; v1(17.425,27.05) 18.36,27.05 19.45,25.96 19.45,22.65 20.6,21.5 ; v1(20.6,18.6) 20.6,21.5 ; R17.2@21.27,21.5 20.6,21.5 ; R31.2@41.3,39.92 41.63,40.25 42.61,40.25 C143.2@42.75,40.39 ; C143.2@42.9,40.37 44.12,40.37 44.275,40.525 44.275,41.975 45.675,43.375 45.675,44.85 v1(45,45.525) ; R260.2@47.8,24.88 47.88,24.8 47.881,24.801 v1(48.352,24.801) 49.419,24.801 49.42,24.8 R259.2@49.5,24.88 ; v1(87.725,22.775) 88.1,22.4 R162.2@88.1,21.705
  Bottom w0.5: CAD2.5@15.4,56.89 16.235,56.89 16.95,56.175 v1(18.825,56.175)
VCC_SCU_1V8: CAD1.1 R14.1 R32.2 R35.2 R36.1 R38.1 R51.2 U1.AA29 | length 46.5
  Top w0.3: v1(28.85,22.05) 29.08,21.82 R35.2@29.7,21.82 ; R32.2@41.7,19.82 42.42,19.82 42.876,20.276 v1(43.927,20.276) ; v1(63.05,22.11) 63.66,22.72 U1.AA29@63.67,22.72
  Top w0.5: v1(42,30.4) R38.1@42.74,30.4 ; v1(42.052,29.126) 42.666,29.126 R36.1@42.74,29.2
  Signal_4 w0.3: v1(42.525,35.55) 42.55,35.525 55.55,35.525 56.05,35.025 56.05,34.425 55.754,34.129 55.429,34.129 v1(55.4,34.1) ; v1(43.927,20.276) 43.927,20.233 44.158,20.002 45.592,20.002 ; 45.592,20.002 47.102,20.002 47.423,20.323 52.274,20.323 52.669,20.718 52.669,20.77 53.599,21.7 56.075,21.7 56.35,21.425 57.96,21.425 58.143,21.608 62.548,21.608 v1(63.05,22.11)
  Bottom w0.3: CAD1.1@39.27,26.41 39.285,26.41 40.175,27.3 40.2,27.275 v1(40.55,27.275) ; R14.1@42.98,19.7 43.41,19.7 43.927,20.217 v1(43.927,20.276) ; v1(55.4,34.1) 57.006,34.1 57.155,34.249 R51.2@57.155,34.8
VDDH1: C53.2 R90.2 R100.2 U11.10 | length 7.5
  Bottom w0.2: U11.10@28.49,28.792 29.168,28.792 29.808,28.152 29.808,27.162 30.275,26.695 30.275,26.125 30.79,25.61 C53.2@30.79,25.6 30.49,25.3 v1(29.75,25.3)
  Bottom w0.3: v1(20.551,25.676) 20.551,25.649 20.725,25.475 R100.2@21.28,25.475 R90.2@21.28,24.475
VDDH2: C71.2 R122.2 R132.2 U12.10 | length 16
  Top w0.2: U12.10@30.5,39.85 30.5,38.611 30.788,38.323 31.663,38.323 31.74,38.4 31.74,38.665 v1(32.175,39.1)
  Top w0.3: R132.2@34.245,47.355 34.265,47.335 R122.2@35.225,47.335 ; R132.2@34.25,47.36 34.25,48.05 v1(34.3,48.1) ; R122.2@35.2,47.36 R122.2@35.225,47.335 ; R122.2@35.4,47.335 R122.2@35.225,47.335
  Signal_8 w0.2: v1(32.175,39.1) 32.65,39.575 32.736,39.575 32.738,39.573 33.112,39.573 33.6,40.061 33.6,41.425 34.8,42.625 34.8,47.6 v1(34.3,48.1)
VDDIO1: C51.2 C52.2 R86.2 R88.2 R92.2 R94.2 R96.2 R98.2 U11.29 | length 22.9
  Top w0.4: v1(18.926,37.377) 18.963,37.377 19.515,36.825 22.48,36.825 v1(22.93,37.275)
  Signal_3 w0.35: v1(18.926,37.377) 18.926,36.129 18.94,36.115 18.324,35.499 18.324,33.933 18.35,33.907 18.35,33.875 17.801,33.326 17.801,32.322 19.373,30.75 19.373,29.627 v1(19.9,29.1)
  Bottom w0.2: R88.2@19.89,36.752 R88.2@19.9,36.762 ; C52.2@20.998,29.592 21.058,29.652 22.53,29.652 U11.29@22.59,29.592
  Bottom w0.3: R98.2@17.84,36.752 R94.2@18.865,36.752 ; v1(18.926,37.377) 18.917,37.377 18.865,37.325 R94.2@18.865,36.752 ; v1(19.9,29.1) C51.2@19.9,29.84 20.16,29.84 20.585,29.415 C52.2@20.85,29.415 ; R86.2@20.915,36.752 R88.2@19.89,36.752 R94.2@18.865,36.752 ; R92.2@21.94,36.752 R96.2@22.965,36.752 22.965,37.24 v1(22.93,37.275)
VDDIO2: C69.2 C70.2 R118.2 R120.2 R124.2 R126.2 R128.2 R130.2 U12.29 | length 7.9
  Top w0.2: C70.2@29.375,47.64 29.375,47.125 v1(29.575,46.925) 29.7,46.8 U12.29@29.7,45.75
  Top w0.3: v1(21.547,50.751) 21.547,50.678 21.6,50.625 R130.2@22.265,50.625 ; v1(21.6,46.075) 22.24,46.075 R128.2@22.24,45.1 ; v1(21.6,47.4) R118.2@22.265,47.4 R120.2@22.265,48.4 ; R126.2@22.265,49.625 R126.2@22.265,49.675 R130.2@22.265,50.625
  Bottom w0.2: C69.2@29.375,47.64 29.375,47.125 v1(29.575,46.925)
VIN: C4.2 FIL1.3 Q7.2 R19.2 R21.2 R22.1 U26.4 U26.8 U27.1 U27.3 | length 75.5
  Signal_3 w0.5: v1(43.75,36.2) 44.507,35.443 44.507,30.852 44.1,30.445 44.1,29.275 46.65,26.725 46.65,22.7 45.825,21.875 44.525,21.875 43.325,20.675 43.325,19.975 v1(44.5,18.8)
  Signal_4 w0.5: v1(44.5,18.8) 44.527,18.827 46.998,18.827 47.172,18.653 51.953,18.653 53.623,20.323 53.623,20.374 53.976,20.727 54.923,20.727 55.973,19.677 55.973,19.676 56.911,18.738 62.688,18.738 64.725,20.775 69.295,20.775 71.699,18.371 73.878,18.371 74.251,17.998 74.749,17.998 75.953,19.202 79.298,19.202 v1(81.15,17.35) v1(81.15,16.65) 81.15,15.85 v1(81.15,15.25)
  Signal_7 w0.4: 82.073,17.993 82.1,18.02
  Bottom w0.3: C4.2@40.75,38.32 41.43,38.32 41.85,37.9 U27.1@41.85,37.38 41.85,36.5 42.15,36.2 v1(43.75,36.2) U27.3@43.75,37.38 ; R22.1@80,15.8 80.3,16.1 U26.4@80.3,17.19 U26.8@80.3,18.1 80.38,18.02 R21.2@81.4,18.02 82.1,18.02
  other v1: 81.15,15.95
VIN_PROT: C1.1 C2.2 C3.2 C6.2 C10.2 C11.2 C12.2 C84.1 C99.2 C104.2 C105.2 C142.2 C147.2 D14.K R1.1 R22.2 R43.2 R47.2 R190.1 U2.3 U3.3 U3.14 U14.7 U18.12 U19.A1 U19.A2 U26.1 U26.2 U26.5 U26.6 U26.7 U31.7 | length 46.5
  Top w0.15: C99.2@70.86,16.45 71.15,16.45 71.6,16.9 U18.12@72.05,16.9
  Top w0.3: v1(70.678,15.051) 70.678,16.218 70.875,16.415 70.85,16.44 C99.2@70.86,16.45
  Top w0.5: R190.1@20.6,45.78 v1(20.6,47.3)
  Bottom w0.2: U3.14@49.7,62.9 U3.3@50.5,62.9 51.4,62.9 51.63,63.13 R43.2@52.3,63.13 ; C104.2@71.13,20.09 71.13,19.57 71.38,19.32 U19.A2@71.38,19.05 ; U19.A1@71.88,19.05 71.88,19.28 72.08,19.48 C105.2@72.08,20.09
  Bottom w0.25: U2.3@36.4,60.44 C6.2@38.25,60.44
  Bottom w0.3: C6.2@38.25,60.44 38.303,60.352 38.325,60.315 38.3,60.29 38.352,60.238 v1(38.352,59.453) ; v1(44.4,60.9) R47.2@44.4,61.62 ; C147.2@46,36.46 C147.2@46.02,36.48 ; v1(46.02,37.42) C147.2@46.02,36.48 ; U31.7@48.755,34.53 48.755,36.745 48.49,37.01 48.22,37.01 48.06,36.85 47.644,36.85 47.484,37.01 46.55,37.01 C147.2@46.02,36.48 ; R1.1@52.025,53.825 52.435,54.235 C2.2@53.325,54.235 C3.2@54.375,54.235 ; R43.2@52.3,63.13 52.62,63.13 52.91,62.84 C12.2@53.3,62.84 53.91,62.84 54.22,62.53 C11.2@54.55,62.53 ; v1(54.225,20.125) 54.715,20.125 C84.1@54.915,19.925 ; U14.7@54.655,21.63 54.655,20.695 54.95,20.4 C84.1@54.95,19.925 ; C1.1@56.5,54.75 56.375,54.875 v1@54.375,54.875 ; C1.1@56.8,54.7 56.8,55.1 v1(55.5,55.1) 54.45,55.1 ; C104.2@71.13,20.09 C105.2@72.08,20.09 72.6,19.57 v1(72.6,19.4) ; D14.K@76.4,17.9 76.6,18.1 78.05,18.1 ; v1(78.05,18.6) 78.05,18.1 ; v1(78.1,17.7) 78.1,18.05 78.05,18.1 ; U26.6@79,17.19 79,17.75 U26.7@79.35,18.1 ; U26.1@79,19.01 79,18.45 U26.7@79.35,18.1 ; U26.5@79.65,17.19 79.65,17.8 U26.7@79.35,18.1 ; U26.2@79.65,19.01 79.65,18.4 U26.7@79.35,18.1 ; v1(54.2,54.775) v1@54.2,54.85 ; v1(54.2,54.775) 54.2,54.41 C3.2@54.375,54.235 ; v1(54.2,54.775) 54.3,54.875 v1@54.375,54.875 ; v1@54.2,54.85 54.2,55.1 ; v1@54.2,54.85 54.375,55.025 ; 54.2,55.1 54.45,55.1 ; 54.2,55.1 v1(54.2,55.35) 54.45,55.1 ; C3.2@54.375,54.235 v1@54.375,54.875 ; v1@54.375,54.875 54.375,55.025 ; 54.375,55.025 54.45,55.1 ; 78.05,18.1 U26.7@79.35,18.1
  Bottom w0.4: C11.2@54.55,62.53 C10.2@56.02,62.53
  other v1: 78.1,16.9 55.8,61.275 56.525,61.275
VLDO2_VSELECT: R232.1 U1.AH13 | length 50.9
  Top w0.127: v1(54.17,43.66) 54.17,43.65 U1.AH13@54.78,43.04
  Signal_8 w0.142: v1(54.17,43.66) 54.891,42.939 56.76,42.939 57.5,42.198 57.5,32.91 57.175,32.585 57.175,32.09 57.6,31.665 57.6,23.65 58.032,23.218 80.802,23.218 81.169,22.851 82.374,22.851 v1(83.4,21.825)
  Bottom w0.127: R232.1@82.7,21.82 82.705,21.825 v1(83.4,21.825)
VLDO4_1V5: J7.6 J7.28 J7.48 R205.1 | length 57.5
  Signal_8 w0.4: v1(49.06,61.12) 50.98,59.2 50.98,51.945 v1(51.625,51.3)
  Signal_4 w0.4: v1(79.925,62.65) 80.487,62.088 87.688,62.088 88.254,62.654 v1(88.254,62.703)
  Signal_7 w0.4: v1(49.06,61.12) 49.12,61.12 49.9,61.9 55.519,61.9 55.571,61.952 56.029,61.952 56.081,61.9 59.964,61.9 60.285,61.579 60.965,61.579 61.279,61.893 67.543,61.893 68.177,62.527 v1(68.554,62.527) 68.554,62.446 68.98,62.02 79.281,62.02 79.911,62.65 v1(79.925,62.65)
  Bottom w0.127: v1(79.925,62.65) 79.925,62.563 80.089,62.399 80.089,61.511 J7.28@80.3,61.3
  Bottom w0.3: v1(51.625,51.3) R205.1@52.52,51.3 ; J7.6@68.3,61.3 68.3,62.65 68.431,62.65 v1(68.554,62.527) ; v1(88.254,62.703) 88.297,62.703 88.3,62.7 J7.48@88.3,61.3
VSYS: R1.2 R219.1 R220.1 U1.AH9 U1.AJ8 U1.B6 | length 69.5
  Top w0.2: v1(48.5,55.9) 48.5,57.139 52.625,61.264 v1(52.625,63.775) ; v1(52.9,50.01) 52.9,50 U1.AJ8@53.51,49.39 U1.AH9@54.78,48.12 ; U1.B6@87.8,51.93 88.46,52.59 88.46,54.56 88.974,55.074 v1(89.381,55.074)
  Signal_4 w0.2: v1(52.625,63.775) 55.85,63.775 57.58,62.045 57.58,61.1 57.905,60.775 60.488,60.775 60.638,60.625 86.125,60.625 88.48,58.27 88.48,56.74 89.381,55.839 v1(89.381,55.074)
  Bottom w0.3: v1(48.5,55.9) 51.04,55.9 R220.1@51.44,55.5 51.44,55.14 R1.2@50.125,53.825 50.15,53.8 R219.1@50.15,52.444 ; R219.1@50.15,52.35 R219.1@50.15,52.444 ; v1(52.9,50.01) 52.31,50.6 51.4,50.6 51,51 51,51.594 R219.1@50.15,52.444
XBEE/EXPANSION_USB2_D_N: L12.2 R77.1 R79.1 U16.5 | length 31.4
  Top w0.132: v1(11.725,40.075) 12,40.35 R77.1@12,41.87 ; R79.1@12.23,22.85 12.23,22.82 v1(12.95,22.1)
  Signal_7 w0.157: v1(11.725,40.075) 12,40.35 12.275,40.35 13.3,39.325 13.3,33.8 11.457,31.957 11.457,29.743 12.907,28.293 12.907,27.719 12.76,27.573 12.76,26.98 12.907,26.834 12.907,26.753 12.441,26.287 12.441,24.034 13.675,22.8 13.675,22.172 13.45,21.947 13.103,21.947 v1(12.95,22.1)
  Bottom w0.132: U16.5@13.775,22.1 v1(12.95,22.1) 12.95,22.05 12.675,21.775 12.55,21.775 12.4,21.925 12.4,22.225 12.4,22.227 cw(c12.549,22.227) 12.549,22.377 12.59,22.377 ccw(c12.59,22.526) 12.739,22.526 12.739,22.56 ccw(c12.59,22.56) 12.59,22.709 12.549,22.709 cw(c12.549,22.858) 12.4,22.858 12.4,22.875 12.4,23.079 12.928,23.607 13.757,23.607 14.05,23.9 14.05,24.175 14.325,24.45 L12.2@14.325,24.727
XBEE/EXPANSION_USB2_D_P: L12.3 R76.1 R78.1 U16.4 | length 31.5
  Top w0.132: R78.1@12.23,21.6 12.775,21.6 v1(12.95,21.425) ; v1(13.2,40.925) 13.525,41.25 R76.1@13.525,41.87
  Signal_7 w0.157: v1(12.95,21.425) 13.103,21.578 13.603,21.578 14.043,22.019 14.043,22.953 12.809,24.187 12.809,26.134 13.275,26.6 13.275,26.868 13.045,27.098 13.045,27.455 13.275,27.685 13.275,28.446 11.825,29.896 11.825,31.804 13.668,33.647 13.668,39.532 12.7,40.5 12.7,40.8 12.825,40.925 v1(13.2,40.925)
  Bottom w0.132: L12.3@13.525,24.727 13.525,24.45 13.682,24.293 13.682,24.053 13.604,23.975 12.775,23.975 12.032,23.232 12.032,21.772 12.397,21.407 12.828,21.407 12.898,21.477 v1(12.95,21.425) 13.225,21.15 U16.4@13.775,21.15
XBEE_D_N: J22.8 R77.2 R240.2 | length 34.7
  Top w0.132: v1(17.38,52.46) 17.188,52.268 16.591,52.268 15.712,51.388 15.645,51.322 cw(c15.507,51.459) 15.37,51.322 15.274,51.418 ccw(c15.136,51.28) 14.999,51.418 14.968,51.387 ccw(c15.106,51.25) 14.968,51.112 15.064,51.016 cw(c14.927,50.879) 15.064,50.741 15.049,50.726 13.585,49.262 13.585,45.734 13.605,45.714 13.605,44.736 13.585,44.716 13.585,44.428 12.782,43.624 12.782,43.453 12.159,42.83 R77.2@12,42.83 12.575,42.255 12.575,41.412 12.414,41.251 12.414,40.165 13.022,39.557 15.543,39.557 16.225,38.875 J22.8@18.417,38.875
  Bottom w0.132: v1(17.38,52.46) 17.264,52.344 17.04,52.344 16.94,52.444 16.94,52.96 17.96,53.98 20.741,53.98 22.253,55.492 23.175,55.492 23.277,55.492 cw(c23.277,55.342) 23.427,55.342 23.427,55.141 ccw(c23.576,55.141) 23.576,54.991 23.61,54.991 ccw(c23.61,55.141) 23.759,55.141 23.759,55.342 cw(c23.908,55.342) 23.908,55.492 23.925,55.492 24.628,55.492 25.084,55.947 25.084,56.209 25.275,56.4 25.62,56.4 R240.2@25.7,56.48
XBEE_D_P: J22.7 R76.2 R241.2 | length 34.7
  Top w0.132: J22.7@15.567,40.875 15.842,41.15 17.1,41.15 17.35,40.9 17.35,39.75 16.9,39.3 16.345,39.3 15.72,39.925 13.175,39.925 12.782,40.318 12.782,41.098 12.943,41.259 12.943,42.248 R76.2@13.525,42.83 13.47,42.83 13.15,43.15 13.15,43.472 13.953,44.275 13.953,44.563 13.973,44.584 13.973,45.866 13.953,45.887 13.953,49.109 16.744,51.9 17.22,51.9 17.28,51.84 v1@17.36,51.84
  Bottom w0.132: v1(17.38,51.86) 17.264,51.976 16.887,51.976 16.572,52.292 16.572,53.113 17.807,54.348 20.588,54.348 22.1,55.86 24.476,55.86 24.716,56.1 24.716,56.36 24.551,56.525 24.145,56.525 R241.2@24.1,56.48
XBEE_ON/SLEEP_N: J23.8 U1.AL24 | length 17.9
  Top w0.127: J23.8@40.417,38.875 43.037,38.875 43.478,38.435 43.84,38.435 46.622,35.653 46.622,32.974 46.584,32.937 46.584,31.041 47.049,30.576 v1(47.052,30.576) ; v1(50.34,28.42) 50.34,28.44 U1.AL24@50.97,29.07
  Bottom w0.127: v1(47.052,30.576) 47.629,30.576 49.785,28.42 v1(50.34,28.42)
XBEE_RESET_N: J22.5 U1.AL25 | length 51.8
  Top w0.127: J22.5@15.567,44.875 v1(17.125,44.875) ; v1(50.35,27.19) 50.36,27.19 U1.AL25@50.97,27.8
  Signal_7 w0.142: v1(17.125,44.875) 21.131,48.881 21.581,48.881 24.011,51.311 25.389,51.311 ; 25.389,51.31 25.963,51.31 ; 25.964,51.311 27.508,51.311 29.082,49.738 30.212,49.738 31.7,48.25 33.169,48.25 37.281,44.139 38.586,44.139 40.344,42.381 40.344,41.177 46.177,35.344 46.189,35.344 46.645,34.888 46.645,32.965 46.629,32.949 46.629,30.153 49,27.782 49.758,27.782 v1(50.35,27.19)
XBEE_SLEEP_RQ: J22.9 U1.AM26 | length 51.2
  Top w0.127: v1(14.78,37.62) 14.78,36.875 J22.9@15.567,36.875 ; v1(49.08,25.92) 49.09,25.92 U1.AM26@49.7,26.53
  Signal_8 w0.142: v1@14.729,37.671 v1(14.78,37.62) 15.692,36.708 15.692,36.033 15.249,35.591 15.249,34.574 14.833,34.159 14.833,33.49 15.239,33.084 15.383,33.084 15.694,32.773 15.694,32.765 16.415,32.044 16.451,32.044 18.789,29.706 18.789,28.924 20.477,27.237 21.173,27.237 21.737,26.673 21.737,26.6 22.278,26.058 22.278,26.026 22.55,25.754 22.554,25.754 23.508,24.8 23.821,24.8 23.868,24.753 29.32,24.753 30.165,23.908 33.727,23.908 35.163,25.344 35.844,25.344 36.375,25.875 36.375,27.495 38.297,29.417 39.992,29.417 40.5,29.925 44.477,29.925 47.702,26.7 48.3,26.7 v1(49.08,25.92)
XBEE_VCC: C37.2 C38.2 J22.1 L22.2 L23.2 | length 15.4
  Top w0.3: J22.1@15.542,52.9 J22.1@15.567,52.875 16.785,52.875 19.102,55.192 19.102,55.608 19.077,55.633 19.077,55.717 19.327,55.967 19.327,56.891 18.6,57.618 v1(18.6,57.647)
  Top w0.4: C37.2@11.8,53.6 12.075,53.325 13.3,53.325 13.725,52.9 ; C38.2@13.725,51.535 13.725,52.9 ; J22.1@15.542,52.9 13.725,52.9
  Bottom w0.3: v1(18.6,57.647) 18.6,58.9 18.825,59.125 L23.2@19.875,59.125
pads on no net: CAD1.7 CAD1.MT1 CAD1.MT2 CAD1.MT3 CAD2.6 CAD2.7 CAD2.8 CAD2.9 CAD2.MT1 CAD2.MT2 CAD2.MT3 D1.4 D1.5 D1.6 D1.7 FIDUCIAL1.1 FIDUCIAL2.1 FIDUCIAL3.1 FIDUCIAL4.1 FIDUCIAL5.1 FIDUCIAL6.1 FIDUCIAL7.1 FIDUCIAL8.1 FIDUCIAL9.1 FIDUCIAL10.1 FIDUCIAL11.1 FIDUCIAL12.1 H1.1 H2.1 H3.1 H4.1 J4.3 J4.4 J7.3 J7.5 J7.7 J7.17 J7.19 J7.42 J7.44 J7.45 J7.46 J7.47 J7.49 J7.51 J7.H1 J7.H2 J7.MT1 J7.MT2 J8.4 J8.8 J8.9 J8.10 J9.6 J9.7 J9.8 J12.MNT1 J12.MNT2 J13.MNT1 J13.MNT2 J14.MT1 J14.MT21 J15.4 J16.MT1 J16.MT21 J17.M1 J17.M2 J19.A8 J19.B8 J23.1 J23.2 J23.3 J23.4 J23.6 J28.10 J28.11 U1.A26 U1.AJ11 U1.AJ13 U1.AK21 U1.AK22 U1.AL18 U1.AL19 U1.AL20 U1.AM10 U1.AM11 U1.AM16 U1.AM17 U1.AM19 U1.AM22 U1.B7 U1.B23 U1.C3 U1.C6 U1.C27 U1.D1 U1.D5 U1.D6 U1.D7 U1.D8 U1.D9 U1.D10 U1.D11 U1.D12 U1.D13 U1.D14 U1.E7 U1.F4 U1.F5 U1.F6 U1.F7 U1.F8 U1.F9 U1.F10 U1.F19 U1.F20 U1.F24 U1.F25 U1.F26 U1.F27 U1.G15 U1.G18 U1.G20 U1.G21 U1.G23 U1.G24 U11.22 U11.25 U11.26 U11.42 U11.43 U11.45 U11.46 U12.22 U12.25 U12.26 U12.42 U12.43 U12.45 U12.46 U13.18 U13.19 U13.20 U13.21 U15.6 U16.6 U18.2 U20.11 U20.12 U20.13 U20.14 U20.28 U20.29 U20.40 U20.41 U20.46 U31.3 U31.5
